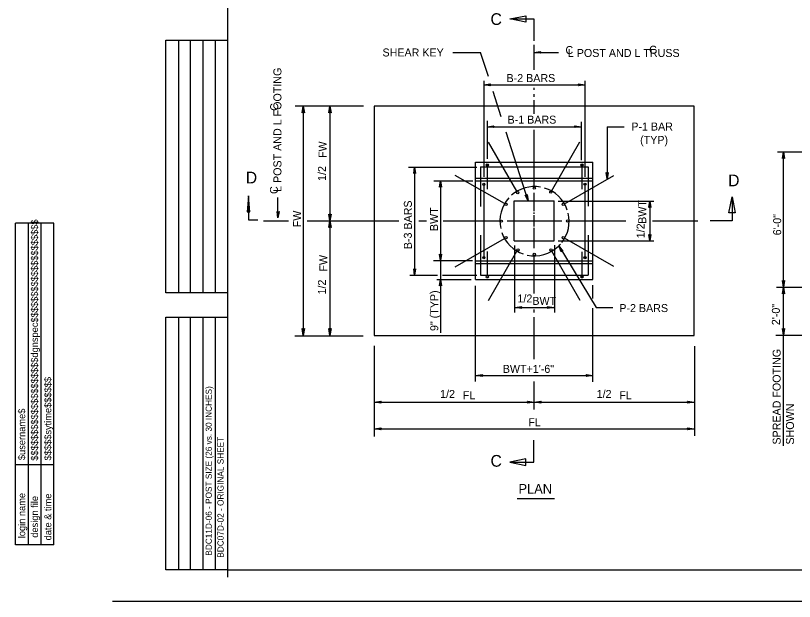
# Model space of a CAD drawing. Extents: x -3 to 26050223, y 0 to 12035012.
# Drawn here: x -3.03 to 21.31, y 0 to 18.31 of the extents above; entities that cross this region are included whole.
import ezdxf

# ---------------------------------------------------------------- set-up
doc = ezdxf.new("R2010")
doc.units = 0
for name, color, linetype in [('1', 7, 'Continuous'), ('2', 7, 'Continuous'), ('39', 7, 'Continuous')]:
    doc.layers.add(name, color=color, linetype=linetype)

msp = doc.modelspace()

# ---------------------------------------------------------------- linework, layer by layer
at = {"layer": '1'}
for p, q in [((3.6, 0.762), (3.6, 42.087)), ((1.667, 9.65), (1.667, 17.55)), ((1.667, 17.55), (3.6, 17.55)), ((2.067, 9.65), (2.067, 17.55)), ((2.433, 9.65), (2.433, 17.55)), ((2.833, 9.65), (2.833, 17.55)), ((3.217, 9.65), (3.217, 17.55)), ((-3.033, 1.767), (-3.033, 11.825)), ((-1.833, 11.825), (-3.033, 11.825)), ((-2.633, 1.767), (-2.633, 11.825)), ((-2.233, 1.767), (-2.233, 11.825)), ((-1.833, 1.767), (-1.833, 11.825)), ((3.6, 9.65), (1.667, 9.65)), ((1.667, 0.983), (1.667, 8.883)), ((1.667, 8.883), (3.6, 8.883)), ((2.067, 0.983), (2.067, 8.883)), ((2.433, 0.983), (2.433, 8.883)), ((2.833, 0.983), (2.833, 8.883)), ((3.217, 0.983), (3.217, 8.883)), ((-1.833, 4.275), (-3.033, 4.275)), ((12.641, 3.22), (13.808, 3.22)), ((-1.833, 1.767), (-3.033, 1.767)), ((3.6, 0.983), (1.667, 0.983)), ((3.6, 0.983), (68.183, 0.983)), ((68.892, 0), (0, 0))]:
    msp.add_line(p, q, dxfattribs=at)
at = {"layer": '39'}
for p, q in [((12.408, 18.211), (12.908, 18.311)), ((12.408, 18.211), (12.908, 18.311)), ((12.908, 18.311), (12.908, 18.111)), ((12.908, 18.311), (12.908, 18.111)), ((12.908, 18.111), (12.408, 18.211)), ((12.908, 18.111), (12.408, 18.211)), ((12.433, 18.211), (13.158, 18.211)), ((13.158, 18.211), (13.158, 17.528)), ((13.175, 16.62), (13.175, 17.403)), ((10.633, 17.161), (11.5, 17.161)), ((11.741, 16.411), (11.5, 17.161)), ((13.166, 17.161), (13.933, 17.161)), ((11.6, 16.278), (11.6, 13.27)), ((11.6, 16.145), (14.758, 16.145)), ((14.758, 16.278), (14.758, 13.278)), ((12.141, 15.145), (11.891, 15.936)), ((13.175, 15.995), (13.175, 16.053)), ((13.175, 15.77), (13.175, 15.853)), ((13.175, 15.245), (13.175, 15.67)), ((7.35, 15.486), (5.708, 15.486)), ((5.958, 15.478), (5.958, 8.311)), ((7.35, 15.486), (6.183, 15.486)), ((6.791, 15.478), (6.791, 11.895)), ((7.841, 15.486), (6.983, 15.486)), ((18.175, 15.478), (8.175, 15.478)), ((8.175, 15.478), (8.175, 8.311)), ((18.175, 8.311), (18.175, 15.478)), ((11.708, 15.02), (11.708, 13.836)), ((14.641, 14.995), (14.641, 13.795)), ((11.708, 14.836), (14.641, 14.836)), ((12.983, 12.52), (12.3, 14.67)), ((13.175, 12.97), (13.175, 14.745)), ((15.45, 14.836), (15.45, 13.211)), ((15.45, 14.836), (15.983, 14.836)), ((12.633, 12.82), (11.75, 14.361)), ((13.716, 12.828), (14.6, 14.37)), ((20.775, 14.053), (25.825, 14.053)), ((20.966, 9.82), (20.966, 14.053)), ((11.341, 10.061), (11.341, 13.728)), ((11.341, 13.728), (15.008, 13.728)), ((11.708, 13.653), (11.708, 12.886)), ((14.666, 13.67), (14.666, 12.886)), ((15.008, 10.061), (15.008, 13.728)), ((9.25, 13.578), (11.383, 13.578)), ((9.433, 13.578), (9.433, 10.195)), ((11.491, 13.586), (14.858, 13.586)), ((11.491, 13.586), (11.491, 12.345)), ((14.858, 13.586), (14.858, 12.353)), ((10.041, 13.145), (11.258, 13.145)), ((10.241, 13.145), (10.241, 10.653)), ((12.25, 12.436), (10.708, 13.311)), ((11.341, 13.228), (15.008, 13.228)), ((11.341, 13.145), (15.008, 13.145)), ((14.116, 12.428), (15.666, 13.311)), ((11.6, 13.036), (11.6, 10.745)), ((14.758, 13.053), (14.758, 10.745)), ((4.245, 12.676), (4.203, 12.176)), ((4.245, 12.676), (4.203, 12.176)), ((4.287, 12.176), (4.245, 12.676)), ((4.287, 12.176), (4.245, 12.676)), ((13.175, 12.195), (13.175, 12.778)), ((4.245, 12.651), (4.245, 11.926)), ((5.166, 11.993), (5.166, 12.626)), ((12.55, 12.52), (13.8, 12.52)), ((12.55, 11.27), (12.55, 12.52)), ((13.8, 11.27), (13.8, 12.52)), ((13.925, 12.511), (16.916, 12.511)), ((16.783, 12.511), (16.783, 11.27)), ((19.258, 12.145), (19.358, 12.645)), ((19.258, 12.145), (19.358, 12.645)), ((19.358, 12.645), (19.458, 12.145)), ((19.358, 12.645), (19.458, 12.145)), ((19.358, 12.62), (19.358, 11.895)), ((4.203, 12.176), (4.287, 12.176)), ((4.203, 12.176), (4.287, 12.176)), ((4.245, 11.926), (4.532, 11.926)), ((13.175, 12.12), (13.175, 12.153)), ((13.175, 11.745), (13.175, 12.078)), ((19.458, 12.145), (19.258, 12.145)), ((19.458, 12.145), (19.258, 12.145)), ((4.719, 11.895), (5.5, 11.895)), ((6.075, 11.895), (7.191, 11.895)), ((6.791, 11.895), (6.791, 8.311)), ((7.141, 11.895), (8.941, 11.895)), ((9.566, 11.895), (9.808, 11.895)), ((10.325, 11.895), (12.1, 11.895)), ((12.325, 11.895), (14.041, 11.895)), ((13.175, 11.895), (13.175, 11.895)), ((13.175, 11.895), (13.175, 11.895)), ((13.175, 11.703), (13.175, 11.72)), ((14.266, 11.895), (16.041, 11.895)), ((16.866, 11.895), (18.291, 11.895)), ((19.358, 11.895), (18.675, 11.895)), ((11.491, 11.453), (11.491, 10.203)), ((13.175, 11.045), (13.175, 11.67)), ((14.858, 11.453), (14.858, 10.203)), ((10.708, 10.461), (12.241, 11.345)), ((12.55, 11.27), (13.8, 11.27)), ((13.925, 11.27), (16.908, 11.27)), ((15.666, 10.47), (14.125, 11.353)), ((11.75, 9.411), (12.633, 10.953)), ((12.558, 11.128), (12.558, 9.036)), ((13.808, 11.136), (13.808, 9.036)), ((13.941, 11.111), (15.108, 9.186)), ((18.175, 10.961), (18.175, 11.103)), ((11.533, 10.936), (11.541, 10.936)), ((11.708, 10.936), (11.708, 10.153)), ((13.175, 9.628), (13.175, 10.803)), ((14.608, 9.411), (13.725, 10.945)), ((14.666, 10.928), (14.666, 10.145)), ((10.025, 10.653), (11.241, 10.653)), ((10.241, 10.653), (10.241, 10.195)), ((11.341, 10.645), (15.008, 10.645)), ((11.341, 10.561), (15.008, 10.561)), ((9.291, 10.195), (10.15, 10.195)), ((10.133, 10.061), (11.208, 10.061)), ((10.241, 10.195), (10.241, 8.395)), ((10.308, 10.195), (11.383, 10.195)), ((11.341, 10.061), (15.008, 10.061)), ((11.491, 10.203), (14.858, 10.203)), ((11.341, 6.878), (11.341, 9.861)), ((15.008, 9.47), (15.008, 9.886)), ((20.741, 9.82), (23.45, 9.82)), ((20.966, 4.861), (20.966, 9.82)), ((12.575, 9.186), (13.791, 9.186)), ((13.175, 9.028), (13.175, 9.128)), ((15.008, 6.861), (15.008, 9.17)), ((15.108, 9.186), (15.633, 9.186)), ((13.175, 7.57), (13.175, 8.886)), ((7.35, 8.295), (5.691, 8.295)), ((7.35, 8.295), (6.183, 8.295)), ((7.825, 8.295), (6.983, 8.295)), ((8.175, 8.311), (18.175, 8.311)), ((20.725, 8.32), (23.483, 8.32)), ((8.175, 7.986), (8.175, 5.153)), ((18.183, 7.978), (18.183, 5.178)), ((11.341, 7.061), (15.008, 7.061)), ((13.175, 6.003), (13.175, 6.878)), ((8.175, 6.228), (13.175, 6.228)), ((13.175, 6.228), (18.175, 6.228)), ((8.175, 5.395), (18.175, 5.395)), ((13.166, 4.353), (13.166, 5.036)), ((12.916, 4.453), (12.416, 4.353)), ((12.916, 4.453), (12.416, 4.353)), ((12.916, 4.253), (12.916, 4.453)), ((12.916, 4.253), (12.916, 4.453)), ((12.416, 4.353), (12.916, 4.253)), ((12.416, 4.353), (12.916, 4.253)), ((12.441, 4.353), (13.166, 4.353))]:
    msp.add_line(p, q, dxfattribs=at)
for points in [[(13.35, 17.161), (13.366, 17.136), (13.166, 17.161), (13.366, 17.195)], [(11.783, 16.145), (11.8, 16.12), (11.6, 16.145), (11.8, 16.178)], [(14.575, 16.145), (14.558, 16.178), (14.758, 16.145), (14.558, 16.12)], [(5.958, 15.286), (5.925, 15.27), (5.958, 15.478), (5.991, 15.27)], [(5.958, 15.286), (5.925, 15.27), (5.958, 15.478), (5.991, 15.27)], [(6.791, 15.286), (6.758, 15.27), (6.791, 15.478), (6.825, 15.27)], [(11.891, 14.836), (11.908, 14.811), (11.708, 14.836), (11.908, 14.87)], [(14.458, 14.836), (14.441, 14.87), (14.641, 14.836), (14.441, 14.811)], [(20.966, 13.861), (20.933, 13.845), (20.966, 14.053), (21, 13.845)], [(9.433, 13.395), (9.408, 13.378), (9.433, 13.578), (9.466, 13.378)], [(9.433, 13.395), (9.408, 13.378), (9.433, 13.578), (9.466, 13.378)], [(15.45, 13.395), (15.483, 13.411), (15.45, 13.211), (15.425, 13.411)], [(10.241, 12.961), (10.216, 12.945), (10.241, 13.145), (10.275, 12.945)], [(10.241, 12.961), (10.216, 12.945), (10.241, 13.145), (10.275, 12.945)], [(12.925, 12.695), (12.95, 12.72), (12.983, 12.52), (12.891, 12.703)], [(16.783, 12.328), (16.758, 12.311), (16.783, 12.511), (16.816, 12.311)], [(16.783, 12.328), (16.758, 12.311), (16.783, 12.511), (16.816, 12.311)], [(5.166, 12.176), (5.199, 12.193), (5.166, 11.993), (5.141, 12.193)], [(6.791, 12.086), (6.825, 12.111), (6.791, 11.895), (6.758, 12.111)], [(6.791, 11.703), (6.758, 11.686), (6.791, 11.895), (6.825, 11.686)], [(16.783, 11.453), (16.816, 11.47), (16.783, 11.27), (16.758, 11.47)], [(16.783, 11.453), (16.816, 11.47), (16.783, 11.27), (16.758, 11.47)], [(14.033, 10.953), (14.016, 10.928), (13.941, 11.111), (14.066, 10.953)], [(10.241, 10.836), (10.275, 10.853), (10.241, 10.653), (10.216, 10.853)], [(9.433, 10.378), (9.466, 10.395), (9.433, 10.195), (9.408, 10.395)], [(10.241, 9.878), (10.216, 9.861), (10.241, 10.061), (10.275, 9.861)], [(20.966, 10.011), (21, 10.036), (20.966, 9.82), (20.933, 10.036)], [(20.966, 9.628), (20.933, 9.611), (20.966, 9.82), (21, 9.611)], [(12.758, 9.186), (12.775, 9.161), (12.575, 9.186), (12.775, 9.22)], [(12.758, 9.186), (12.775, 9.161), (12.575, 9.186), (12.775, 9.22)], [(13.608, 9.186), (13.591, 9.22), (13.791, 9.186), (13.591, 9.161)], [(13.608, 9.186), (13.591, 9.22), (13.791, 9.186), (13.591, 9.161)], [(5.958, 8.503), (5.991, 8.528), (5.958, 8.311), (5.925, 8.528)], [(5.958, 8.503), (5.991, 8.528), (5.958, 8.311), (5.925, 8.528)], [(6.791, 8.503), (6.825, 8.528), (6.791, 8.311), (6.758, 8.528)], [(6.791, 8.503), (6.825, 8.528), (6.791, 8.311), (6.758, 8.528)], [(20.966, 8.511), (21, 8.536), (20.966, 8.32), (20.933, 8.536)], [(11.533, 7.061), (11.558, 7.028), (11.341, 7.061), (11.558, 7.095)], [(14.816, 7.061), (14.8, 7.095), (15.008, 7.061), (14.8, 7.028)], [(8.366, 6.228), (8.391, 6.195), (8.175, 6.228), (8.391, 6.261)], [(12.983, 6.228), (12.966, 6.261), (13.175, 6.228), (12.966, 6.195)], [(13.366, 6.228), (13.391, 6.195), (13.175, 6.228), (13.391, 6.261)], [(17.983, 6.228), (17.966, 6.261), (18.175, 6.228), (17.966, 6.195)], [(8.366, 5.395), (8.391, 5.361), (8.175, 5.395), (8.391, 5.428)], [(17.983, 5.395), (17.966, 5.428), (18.175, 5.395), (17.966, 5.361)]]:
    msp.add_lwpolyline(points, close=True, dxfattribs=at)
for centre in [(11.708, 13.645), (14.666, 13.645), (11.6, 13.036), (13.175, 12.92), (14.758, 13.045), (12.658, 12.778), (13.691, 12.795), (12.291, 12.411), (14.083, 12.411), (14.216, 11.895), (12.15, 11.886), (12.291, 11.37), (14.083, 11.37), (12.666, 10.986), (13.7, 10.986), (11.6, 10.745), (13.175, 10.853), (14.758, 10.745), (11.708, 10.145), (14.666, 10.145)]:
    msp.add_circle(centre, 0.0344, dxfattribs=at)
for start, end in [(80.2569, 131.4173), (18.8491, 73.3856), (137.5169, 192.4381), (322.2419, 13.3424), (199.2693, 251.1509), (257.7537, 313.7939), (315, 318.698)]:
    msp.add_arc((13.183, 11.886), 1.083, start, end, dxfattribs=at)

# ---------------------------------------------------------------- texts
at = {"layer": '1'}
for s, height, p in [('$$$$$$$$$$$$$$$$$$$$dgnspec$$$$$$$$$$$$$$$$$$$$', 0.21665, (-2.333, 4.4)), ('$$$$$sytime$$$$$$', 0.21665, (-1.917, 4.408)), ('BDC11D-06 - POST SIZE (26 vs. 30 INCHES) ', 0.19265, (3.098, 1.431)), ('$username$', 0.2167, (-2.733, 4.417)), ('BDC07D-02 - ORIGINAL SHEET', 0.19265, (3.467, 1.367)), ('login name', 0.2167, (-2.733, 1.975)), ('design file', 0.21665, (-2.333, 1.992)), ('date & time', 0.21665, (-1.917, 1.908))]:
    msp.add_text(s, height=height, rotation=90, dxfattribs=at).set_placement(p)
at = {"layer": '2'}
for s, height, p in [('C', 0.367, (11.808, 18.02)), ('SHEAR KEY', 0.25, (8.433, 17.036)), ('C', 0.25, (14.15, 17.111)), ('C', 0.25, (16.766, 17.12)), ('L POST AND L TRUSS', 0.25, (14.225, 17.02)), ('B-2 BARS', 0.25, (12.308, 16.236)), ('B-1 BARS', 0.25, (12.341, 14.936)), ('P-1 BAR', 0.25, (16.208, 14.72)), ('(TYP)', 0.25, (16.483, 14.303)), ('D', 0.367, (4.161, 13.066)), ('D', 0.367, (19.233, 12.978)), ('1/2', 0.25, (12.65, 9.345)), ('BWT', 0.25, (13.116, 9.27)), ('P-2 BARS', 0.25, (15.833, 9.045)), ('BWT+1\'-6"', 0.25, (12.191, 7.145)), ('1/2', 0.25, (10.233, 6.361)), ('1/2', 0.25, (15.125, 6.361)), ('FL', 0.25, (10.941, 6.32)), ('FL', 0.25, (15.833, 6.32)), ('FL', 0.25, (12.991, 5.478)), ('C', 0.367, (11.808, 4.211))]:
    msp.add_text(s, height=height, dxfattribs=at).set_placement(p)
for s, height, p in [('L POST AND L FOOTING', 0.25, (5.274, 12.803)), ('C', 0.25, (5.174, 15.336)), ('FW', 0.25, (6.683, 13.861)), ('1/2', 0.25, (6.666, 13.145)), ('C', 0.25, (5.166, 12.736)), ('B-3 BARS', 0.25, (9.35, 11.011)), ('BWT', 0.25, (16.675, 11.803)), ('FW', 0.2499, (5.891, 11.695)), ('BWT', 0.25, (10.166, 11.578)), ('6\'-0"', 0.25, (20.891, 11.445)), ('1/2', 0.25, (16.625, 11.353)), ('FW', 0.25, (6.708, 10.311)), ('1/2', 0.25, (6.666, 9.595)), ('9" (TYP)', 0.25, (10.175, 8.453)), ('2\'-0"', 0.25, (20.85, 8.636)), ('SPREAD FOOTING', 0.25, (20.875, 4.903)), ('SHOWN', 0.25, (21.291, 4.903))]:
    msp.add_text(s, height=height, rotation=90, dxfattribs=at).set_placement(p)
at = {"layer": '39'}
msp.add_text('PLAN', height=0.3, dxfattribs=at).set_placement((12.683, 3.37))

doc.saveas('drawing.dxf')
